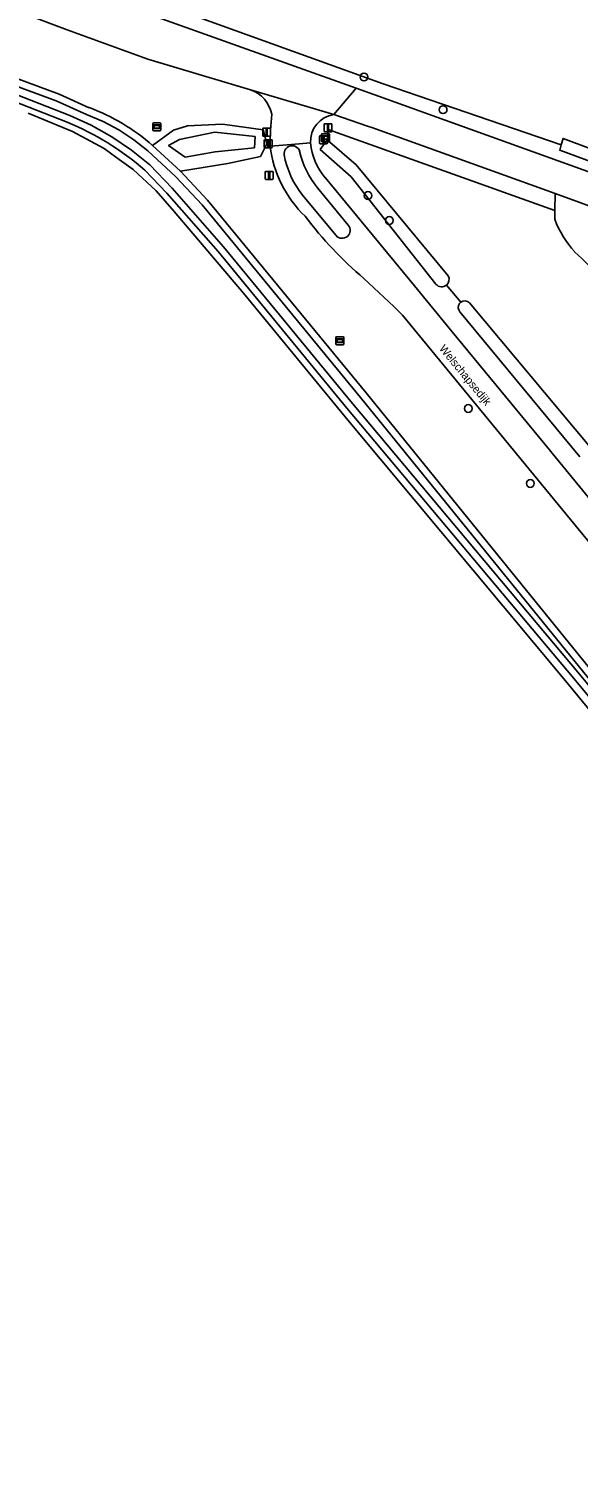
# Model space of a CAD drawing. Extents: x 156061 to 157804, y 383437 to 385640.
# Drawn here: x 156563.1 to 156631.9, y 384902.7 to 385081.3 of the extents above; entities that cross this region are included whole.
import ezdxf

# ---------------------------------------------------------------- set-up
doc = ezdxf.new("R2010")
doc.units = 0
for name, color, linetype in [('IMGEO_Afsluitpaal', 7, 'Continuous'), ('IMGEO_Berm_groen', 7, 'Continuous'), ('IMGEO_Boom', 7, 'Continuous'), ('IMGEO_Fietspad_gesloten', 7, 'Continuous'), ('IMGEO_Fietspad_open', 7, 'Continuous'), ('IMGEO_Grasland_overig', 7, 'Continuous'), ('IMGEO_Groenvoorziening', 7, 'Continuous'), ('IMGEO_Loofbos', 7, 'Continuous'), ('IMGEO_Oever', 7, 'Continuous'), ('IMGEO_Openbare_ruimte_label', 7, 'Continuous'), ('IMGEO_Rijbaan_lokaal_gesloten', 7, 'Continuous'), ('IMGEO_Rijbaan_lokaal_open', 7, 'Continuous'), ('IMGEO_Verkeersbordpaal', 7, 'Continuous'), ('IMGEO_Verkeerseiland_open', 7, 'Continuous'), ('IMGEO_Verklikker', 7, 'Continuous'), ('IMGEO_Waterloop', 7, 'Continuous')]:
    doc.layers.add(name, color=color, linetype=linetype)

msp = doc.modelspace()

# ---------------------------------------------------------------- linework, layer by layer
at = {"layer": 'IMGEO_Afsluitpaal'}
for p, q in [((156592.74, 385067.38), (156593.53, 385067.38)), ((156593.53, 385067.38), (156592.74, 385067.38)), ((156592.64, 385066.48), (156592.64, 385067.28)), ((156592.64, 385067.28), (156592.64, 385066.48)), ((156593.53, 385066.38), (156592.74, 385066.38)), ((156592.74, 385066.38), (156593.53, 385066.38)), ((156593.63, 385067.28), (156593.63, 385066.48)), ((156593.63, 385066.48), (156593.63, 385067.28))]:
    msp.add_line(p, q, dxfattribs=at)
msp.add_lwpolyline([(156593.06, 385067.26), (156593.21, 385067.26), (156593.21, 385066.51), (156593.06, 385066.51), (156593.06, 385067.26)], dxfattribs=at)
for centre, start, end in [((156592.74, 385067.28), 90, 180), ((156592.74, 385067.28), 90, 180), ((156593.53, 385067.28), 0, 90), ((156593.53, 385067.28), 360, 90), ((156592.74, 385066.48), 180, 270), ((156592.74, 385066.48), 180, 270), ((156593.53, 385066.48), 270, 0), ((156593.53, 385066.48), 270, 0)]:
    msp.add_arc(centre, 0.1, start, end, dxfattribs=at)
at = {"layer": 'IMGEO_Berm_groen'}
for points in [[(156614.11, 385049.31), (156603.5, 385062.72), (156599.64, 385066.17), (156600.1, 385066.78), (156600.53, 385067.34), (156600.64, 385068.65), (156628.99, 385058.53), (156629, 385060.65), (156606.09, 385068.91), (156605.55, 385069.09), (156601.32, 385070.53)], [(156600.26, 385062.64), (156611.41, 385049.1), (156616.13, 385043.37), (156628.31, 385028.6), (156628.66, 385028.19), (156634.53, 385021.05), (156651.9, 385000), (156717.24, 384920.7), (156766.23, 384861.24), (156857.95, 384750), (156913.26, 384682.92), (156945.25, 384644.12), (156951.65, 384636.45), (156952.01, 384636.1)], [(156617.04, 385046.91), (156617.2, 385047.08), (156615.41, 385049.21)], [(156632.12, 385027.75), (156617.11, 385045.87)]]:
    msp.add_lwpolyline(points, dxfattribs=at)
for centre, radius, start, end in [((156601.86, 385067.14), 3.44, 99.135, 182.563), ((156606.15, 385067.67), 7.75, 185.1159, 220.5408), ((156614.81, 385049.94), 0.942, 221.7637, 309.6405), ((156617.7, 385046.43), 0.815, 144.1901, 223.9343)]:
    msp.add_arc(centre, radius, start, end, dxfattribs=at)
at = {"layer": 'IMGEO_Boom'}
for centre in [(156605.11, 385075.21), (156615, 385071.13), (156605.6, 385060.4), (156608.27, 385057.28), (156618.16, 385033.78), (156625.91, 385024.41)]:
    msp.add_circle(centre, 0.489, dxfattribs=at)
at = {"layer": 'IMGEO_Fietspad_gesloten'}
for points in [[(156598.43, 385066.98), (156596.03, 385066.78), (156593.38, 385066.58)], [(156913.26, 384682.92), (156857.95, 384750), (156766.23, 384861.24), (156717.24, 384920.7), (156651.9, 385000), (156634.53, 385021.05), (156628.66, 385028.19), (156628.31, 385028.6), (156616.13, 385043.37), (156611.41, 385049.1), (156600.26, 385062.64)], [(156601.61, 385055.39), (156597.42, 385060.46)], [(156599.31, 385061.36), (156603.14, 385056.71)], [(156605.09, 385050.03), (156608.82, 385046.51), (156609.37, 385045.98), (156609.93, 385045.44), (156647.34, 385000), (156714.45, 384918.5), (156763.61, 384858.81), (156853.32, 384750), (156910.52, 384680.62), (156937.97, 384647.33)]]:
    msp.add_lwpolyline(points, dxfattribs=at)
for centre, radius, start, end in [((156607.94, 385068.37), 14.68, 186.9996, 226.026), ((156596.12, 385065.62), 1.01, 94.4691, 187.3279), ((156596.09, 385065.59), 1.04, 20.9304, 92.8641), ((156607.81, 385068.36), 11.02, 192.6008, 219.4784), ((156606.15, 385067.67), 7.75, 185.1159, 220.5408), ((156606.42, 385067.61), 11.5, 190.6035, 218.4404), ((156637.68, 385088.16), 50.16, 217.2427, 229.4737), ((156602.37, 385056.06), 1.01, 221.1018, 40.3826)]:
    msp.add_arc(centre, radius, start, end, dxfattribs=at)
at = {"layer": 'IMGEO_Fietspad_open'}
for points in [[(156601.32, 385070.53), (156590.93, 385073.63)], [(156593.38, 385066.58), (156596.03, 385066.78), (156598.43, 385066.98)]]:
    msp.add_lwpolyline(points, dxfattribs=at)
for centre, radius, start, end in [((156589.47, 385069.69), 4.2, 12.2727, 69.6849), ((156628.6, 385066.88), 35.22, 173.9637, 180.4885), ((156601.86, 385067.14), 3.44, 99.135, 182.563)]:
    msp.add_arc(centre, radius, start, end, dxfattribs=at)
at = {"layer": 'IMGEO_Grasland_overig'}
msp.add_lwpolyline([(156632.09, 385059.53), (156629, 385060.65), (156628.99, 385058.53), (156628.98, 385057.43)], dxfattribs=at)
for centre, radius, start, end in [((156640.28, 385061.53), 12.01, 199.9286, 222.6911), ((156680.81, 385103.13), 70.08, 225.225, 241.5085)]:
    msp.add_arc(centre, radius, start, end, dxfattribs=at)
at = {"layer": 'IMGEO_Groenvoorziening'}
for points in [[(156590.93, 385073.63), (156578.06, 385077.45), (156567.97, 385081.12), (156557.53, 385085.07), (156500, 385105.74), (156431.78, 385130.12), (156326.22, 385167.86), (156324.12, 385168.82), (156320.16, 385170.64)], [(156316.34, 385168.65), (156316.47, 385168.61), (156317.11, 385168.38), (156326.93, 385164.88), (156430.96, 385127.58), (156429.85, 385123.97), (156435.06, 385119.83), (156500, 385096.91), (156553.67, 385077.98), (156566.96, 385073.06), (156570.74, 385071.38)], [(156695.72, 385041.75), (156689.55, 385043.91), (156629.6, 385066.07), (156629.79, 385066.73), (156607.49, 385074.38), (156566.3, 385089.23)], [(156566.3, 385089.23), (156607.49, 385074.38), (156629.79, 385066.73), (156630.02, 385067.53), (156690.52, 385044.95), (156696.35, 385043.19)], [(156569.75, 385086.11), (156604.14, 385073.81), (156606.92, 385072.81), (156634.59, 385062.86), (156662.26, 385052.85), (156695.62, 385040.8)], [(156567.98, 385069.56), (156552.81, 385075.49)], [(156563.11, 385070.71), (156568.65, 385068.4), (156572.59, 385066.26), (156574.17, 385065.13), (156576.25, 385063.65), (156579.11, 385060.99), (156581.38, 385058.42), (156590.03, 385048.18), (156603.33, 385032.02), (156630.11, 385000), (156664.3, 384958.48)], [(156719.79, 384891.58), (156704.18, 384910.35), (156680.54, 384938.81), (156675.71, 384944.62), (156664.3, 384958.48), (156630.11, 385000), (156603.33, 385032.02), (156590.03, 385048.18), (156581.38, 385058.42), (156579.11, 385060.99), (156576.25, 385063.65), (156574.17, 385065.13), (156572.59, 385066.26), (156568.65, 385068.4), (156563.11, 385070.71)], [(156578.66, 385066.65), (156581.27, 385068.56), (156583.03, 385069.11), (156587.41, 385069.33), (156592.51, 385068.62), (156592.95, 385066.88), (156592.16, 385065.26), (156588.06, 385064.39), (156582.15, 385063.43), (156585.55, 385059.83), (156605.37, 385035.73), (156634.41, 385000), (156674.27, 384951.34), (156673.48, 384950.41), (156679.88, 384942.66), (156680.72, 384943.26), (156697.98, 384923.07), (156706.71, 384912.4), (156835.46, 384755.03)], [(156658.27, 384967.54), (156631.39, 385000), (156602.97, 385033.81), (156586.86, 385053.4), (156580.46, 385060.7), (156577.71, 385063.59)], [(156763.61, 384858.81), (156714.45, 384918.5), (156647.34, 385000), (156609.93, 385045.44), (156609.37, 385045.98), (156608.82, 385046.51), (156605.09, 385050.03)]]:
    msp.add_lwpolyline(points, dxfattribs=at)
for points in [[(156588.06, 385064.39), (156592.16, 385065.26), (156592.95, 385066.88), (156592.51, 385068.62), (156587.41, 385069.33), (156583.03, 385069.11), (156581.27, 385068.56), (156578.66, 385066.65), (156582.15, 385063.43)], [(156582.75, 385065.21), (156580.66, 385066.66), (156582.02, 385067.42), (156586.46, 385068.33), (156591.48, 385067.77), (156591.39, 385066.37), (156586.48, 385065.86)]]:
    msp.add_lwpolyline(points, close=True, dxfattribs=at)
for centre, radius, start, end in [((156589.47, 385069.69), 4.2, 12.2727, 69.6849), ((156561.98, 385047.76), 25.2, 48.5596, 69.6683), ((156554.66, 385036.95), 35.22, 49.1343, 67.7901), ((156628.6, 385066.88), 35.22, 173.9637, 180.4885), ((156607.94, 385068.37), 14.68, 186.9996, 226.026), ((156637.68, 385088.16), 50.16, 217.2427, 229.4737)]:
    msp.add_arc(centre, radius, start, end, dxfattribs=at)
at = {"layer": 'IMGEO_Loofbos'}
for points in [[(156628.98, 385057.43), (156628.99, 385058.53), (156600.64, 385068.65), (156600.53, 385067.34), (156604.12, 385064.23), (156615.65, 385050.37)], [(156615.41, 385049.21), (156617.2, 385047.08)], [(156618.31, 385046.97), (156633.42, 385028.9)]]:
    msp.add_lwpolyline(points, dxfattribs=at)
for centre, radius, start, end in [((156640.28, 385061.53), 12.01, 199.9286, 222.6911), ((156680.81, 385103.13), 70.08, 225.225, 241.5085), ((156614.81, 385049.94), 0.943, 309.5792, 27.3071), ((156617.7, 385046.41), 0.829, 42.3292, 126.9751)]:
    msp.add_arc(centre, radius, start, end, dxfattribs=at)
at = {"layer": 'IMGEO_Oever'}
for points in [[(156435.06, 385119.83), (156393.97, 385075.53), (156396.11, 385073.31), (156435.74, 385116.68), (156500, 385094.07), (156552.81, 385075.49), (156567.98, 385069.56)], [(156570.74, 385071.38), (156566.96, 385073.06), (156553.67, 385077.98), (156500, 385096.91), (156435.06, 385119.83)], [(156553.36, 385077.12), (156566.62, 385072.22), (156570.39, 385070.54), (156572.46, 385069.67), (156574.43, 385068.61), (156576.3, 385067.38), (156578.05, 385065.97), (156581.52, 385062.79), (156584.87, 385059.23), (156604.67, 385035.16), (156633.71, 384999.43), (156673.09, 384951.35), (156672.81, 384951.02), (156658.97, 384968.11), (156632.08, 385000.58), (156603.67, 385034.39), (156587.55, 385053.99), (156581.13, 385061.31), (156578.33, 385064.24), (156576.03, 385066.09), (156573.58, 385067.73), (156571, 385069.18), (156568.31, 385070.4), (156553.13, 385076.34)], [(156577.71, 385063.59), (156580.46, 385060.7), (156586.86, 385053.4), (156602.97, 385033.81), (156631.39, 385000), (156658.27, 384967.54), (156672.8, 384949.6), (156673.48, 384950.41), (156674.27, 384951.34), (156634.41, 385000), (156605.37, 385035.73), (156585.55, 385059.83), (156582.15, 385063.43), (156578.66, 385066.65)]]:
    msp.add_lwpolyline(points, dxfattribs=at)
for centre, radius, start, end in [((156561.98, 385047.76), 25.2, 48.5596, 69.6683), ((156554.66, 385036.95), 35.22, 49.1343, 67.7901)]:
    msp.add_arc(centre, radius, start, end, dxfattribs=at)
at = {"layer": 'IMGEO_Rijbaan_lokaal_gesloten'}
msp.add_lwpolyline([(156337.29, 385169.36), (156325.8, 385173.38), (156324.12, 385168.82), (156326.22, 385167.86), (156431.78, 385130.12), (156500, 385105.74), (156557.53, 385085.07), (156567.97, 385081.12), (156578.06, 385077.45), (156590.93, 385073.63), (156601.32, 385070.53), (156604.14, 385073.81), (156569.75, 385086.11)], dxfattribs=at)
at = {"layer": 'IMGEO_Rijbaan_lokaal_open'}
msp.add_lwpolyline([(156771.27, 385013.26), (156725.73, 385029.79), (156717.59, 385032.82), (156695.62, 385040.8), (156662.26, 385052.85), (156634.59, 385062.86), (156606.92, 385072.81), (156604.14, 385073.81), (156601.32, 385070.53), (156605.55, 385069.09), (156606.09, 385068.91), (156629, 385060.65), (156632.09, 385059.53), (156634.02, 385058.83), (156661.06, 385049.07), (156703.57, 385033.62), (156724.41, 385026.09), (156770.02, 385009.53)], dxfattribs=at)
at = {"layer": 'IMGEO_Verkeersbordpaal'}
for p, q in [((156600.11, 385068.48), (156600.11, 385069.28)), ((156600.11, 385069.28), (156600.11, 385068.48)), ((156600.21, 385069.38), (156601, 385069.38)), ((156601, 385069.38), (156600.21, 385069.38)), ((156601.1, 385069.28), (156601.1, 385068.48)), ((156601.1, 385068.48), (156601.1, 385069.28)), ((156592.44, 385067.91), (156592.44, 385068.71)), ((156592.44, 385068.71), (156592.44, 385067.91)), ((156592.54, 385068.81), (156593.33, 385068.81)), ((156593.33, 385068.81), (156592.54, 385068.81)), ((156593.33, 385067.81), (156592.54, 385067.81)), ((156592.54, 385067.81), (156593.33, 385067.81)), ((156593.43, 385068.71), (156593.43, 385067.91)), ((156593.43, 385067.91), (156593.43, 385068.71)), ((156599.55, 385066.98), (156599.55, 385067.78)), ((156599.55, 385067.78), (156599.55, 385066.98)), ((156599.65, 385067.88), (156600.44, 385067.88)), ((156600.44, 385067.88), (156599.65, 385067.88)), ((156601, 385068.38), (156600.21, 385068.38)), ((156600.21, 385068.38), (156601, 385068.38)), ((156600.54, 385067.78), (156600.54, 385066.98)), ((156600.54, 385066.98), (156600.54, 385067.78)), ((156600.44, 385066.88), (156599.65, 385066.88)), ((156599.65, 385066.88), (156600.44, 385066.88)), ((156592.74, 385062.52), (156592.74, 385063.32)), ((156592.74, 385063.32), (156592.74, 385062.52)), ((156592.84, 385063.42), (156593.63, 385063.42)), ((156593.63, 385063.42), (156592.84, 385063.42)), ((156593.63, 385062.42), (156592.84, 385062.42)), ((156592.84, 385062.42), (156593.63, 385062.42)), ((156593.73, 385063.32), (156593.73, 385062.52)), ((156593.73, 385062.52), (156593.73, 385063.32))]:
    msp.add_line(p, q, dxfattribs=at)
for points in [[(156600.53, 385069.26), (156600.68, 385069.26), (156600.68, 385068.51), (156600.53, 385068.51), (156600.53, 385069.26)], [(156592.86, 385068.69), (156593.01, 385068.69), (156593.01, 385067.94), (156592.86, 385067.94), (156592.86, 385068.69)], [(156599.97, 385067.76), (156600.12, 385067.76), (156600.12, 385067.01), (156599.97, 385067.01), (156599.97, 385067.76)], [(156593.16, 385063.29), (156593.31, 385063.29), (156593.31, 385062.54), (156593.16, 385062.54), (156593.16, 385063.29)]]:
    msp.add_lwpolyline(points, dxfattribs=at)
for centre, start, end in [((156600.21, 385069.28), 90, 180), ((156600.21, 385069.28), 90, 180), ((156601, 385069.28), 0, 90), ((156601, 385069.28), 360, 90), ((156592.54, 385068.71), 90, 180), ((156592.54, 385068.71), 90, 180), ((156592.54, 385067.91), 180, 270), ((156592.54, 385067.91), 180, 270), ((156593.33, 385068.71), 0, 90), ((156593.33, 385068.71), 360, 90), ((156593.33, 385067.91), 270, 0), ((156593.33, 385067.91), 270, 0), ((156599.65, 385067.78), 90, 180), ((156599.65, 385067.78), 90, 180), ((156600.21, 385068.48), 180, 270), ((156600.21, 385068.48), 180, 270), ((156600.44, 385067.78), 0, 90), ((156600.44, 385067.78), 360, 90), ((156601, 385068.48), 270, 0), ((156601, 385068.48), 270, 0), ((156599.65, 385066.98), 180, 270), ((156599.65, 385066.98), 180, 270), ((156600.44, 385066.98), 270, 0), ((156600.44, 385066.98), 270, 0), ((156592.84, 385063.32), 90, 180), ((156592.84, 385063.32), 90, 180), ((156592.84, 385062.52), 180, 270), ((156592.84, 385062.52), 180, 270), ((156593.63, 385063.32), 0, 90), ((156593.63, 385063.32), 360, 90), ((156593.63, 385062.52), 270, 0), ((156593.63, 385062.52), 270, 0)]:
    msp.add_arc(centre, 0.1, start, end, dxfattribs=at)
at = {"layer": 'IMGEO_Verkeerseiland_open'}
for points in [[(156597.42, 385060.46), (156601.61, 385055.39)], [(156603.14, 385056.71), (156599.31, 385061.36)]]:
    msp.add_lwpolyline(points, dxfattribs=at)
for centre, radius, start, end in [((156596.12, 385065.62), 1.01, 94.4691, 187.3279), ((156596.09, 385065.59), 1.04, 20.9304, 92.8641), ((156607.81, 385068.36), 11.02, 192.6008, 219.4784), ((156606.42, 385067.61), 11.5, 190.6035, 218.4404), ((156602.37, 385056.06), 1.01, 221.1018, 40.3826)]:
    msp.add_arc(centre, radius, start, end, dxfattribs=at)
at = {"layer": 'IMGEO_Verklikker'}
for p, q in [((156578.7, 385068.59), (156578.7, 385069.39)), ((156578.7, 385069.39), (156578.7, 385068.59)), ((156578.8, 385069.49), (156579.59, 385069.49)), ((156579.59, 385069.49), (156578.8, 385069.49)), ((156579.69, 385069.39), (156579.69, 385068.59)), ((156579.69, 385068.59), (156579.69, 385069.39)), ((156579.59, 385068.49), (156578.8, 385068.49)), ((156578.8, 385068.49), (156579.59, 385068.49)), ((156599.8, 385067.23), (156599.8, 385068.03)), ((156599.8, 385068.03), (156599.8, 385067.23)), ((156599.9, 385068.13), (156600.69, 385068.13)), ((156600.69, 385068.13), (156599.9, 385068.13)), ((156600.79, 385068.03), (156600.79, 385067.23)), ((156600.79, 385067.23), (156600.79, 385068.03)), ((156600.69, 385067.13), (156599.9, 385067.13)), ((156599.9, 385067.13), (156600.69, 385067.13)), ((156601.59, 385041.85), (156601.59, 385042.65)), ((156601.59, 385042.65), (156601.59, 385041.85)), ((156601.69, 385042.75), (156602.48, 385042.75)), ((156602.48, 385042.75), (156601.69, 385042.75)), ((156602.58, 385042.65), (156602.58, 385041.85)), ((156602.58, 385041.85), (156602.58, 385042.65)), ((156602.48, 385041.75), (156601.69, 385041.75)), ((156601.69, 385041.75), (156602.48, 385041.75))]:
    msp.add_line(p, q, dxfattribs=at)
for points in [[(156578.8, 385069.22), (156579.59, 385069.22), (156579.59, 385068.76), (156578.8, 385068.76), (156578.8, 385069.22)], [(156578.87, 385069.16), (156578.87, 385068.82), (156579.53, 385068.82), (156579.53, 385069.16), (156578.87, 385069.16)], [(156599.9, 385067.86), (156600.69, 385067.86), (156600.69, 385067.4), (156599.9, 385067.4), (156599.9, 385067.86)], [(156599.97, 385067.8), (156599.97, 385067.46), (156600.62, 385067.46), (156600.62, 385067.8), (156599.97, 385067.8)], [(156601.7, 385042.48), (156602.48, 385042.48), (156602.48, 385042.02), (156601.7, 385042.02), (156601.7, 385042.48)], [(156601.76, 385042.42), (156601.76, 385042.08), (156602.42, 385042.08), (156602.42, 385042.42), (156601.76, 385042.42)]]:
    msp.add_lwpolyline(points, dxfattribs=at)
for centre, start, end in [((156578.8, 385069.39), 90, 180), ((156578.8, 385069.39), 90, 180), ((156579.59, 385069.39), 0, 90), ((156579.59, 385069.39), 360, 90), ((156578.8, 385068.59), 180, 270), ((156578.8, 385068.59), 180, 270), ((156579.59, 385068.59), 270, 0), ((156579.59, 385068.59), 270, 0), ((156599.9, 385068.03), 90, 180), ((156599.9, 385068.03), 90, 180), ((156600.69, 385068.03), 0, 90), ((156600.69, 385068.03), 360, 90), ((156599.9, 385067.23), 180, 270), ((156599.9, 385067.23), 180, 270), ((156600.69, 385067.23), 270, 0), ((156600.69, 385067.23), 270, 0), ((156601.69, 385042.65), 90, 180), ((156601.69, 385042.65), 90, 180), ((156602.48, 385042.65), 0, 90), ((156602.48, 385042.65), 360, 90), ((156601.69, 385041.85), 180, 270), ((156601.69, 385041.85), 180, 270), ((156602.48, 385041.85), 270, 0), ((156602.48, 385041.85), 270, 0)]:
    msp.add_arc(centre, 0.1, start, end, dxfattribs=at)
at = {"layer": 'IMGEO_Waterloop'}
for points in [[(156553.13, 385076.34), (156568.31, 385070.4), (156571, 385069.18), (156573.58, 385067.73), (156576.03, 385066.09), (156578.33, 385064.24), (156581.13, 385061.31), (156587.55, 385053.99), (156603.67, 385034.39), (156632.08, 385000.58), (156658.97, 384968.11), (156672.81, 384951.02), (156673.09, 384951.35), (156633.71, 384999.43), (156604.67, 385035.16), (156584.87, 385059.23), (156581.52, 385062.79), (156578.05, 385065.97), (156576.3, 385067.38), (156574.43, 385068.61), (156572.46, 385069.67), (156570.39, 385070.54), (156566.62, 385072.22), (156553.36, 385077.12)], [(156604.12, 385064.23), (156600.53, 385067.34), (156600.1, 385066.78), (156599.64, 385066.17), (156603.5, 385062.72), (156614.11, 385049.31)], [(156630.02, 385067.53), (156629.79, 385066.73), (156629.6, 385066.07), (156689.55, 385043.91), (156695.72, 385041.75)], [(156696.35, 385043.19), (156690.52, 385044.95), (156630.02, 385067.53)], [(156615.65, 385050.37), (156604.12, 385064.23)], [(156617.2, 385047.08), (156617.04, 385046.91)], [(156633.42, 385028.9), (156618.31, 385046.97)], [(156617.11, 385045.87), (156632.12, 385027.75)]]:
    msp.add_lwpolyline(points, dxfattribs=at)
msp.add_lwpolyline([(156582.75, 385065.21), (156586.48, 385065.86), (156591.39, 385066.37), (156591.48, 385067.77), (156586.46, 385068.33), (156582.02, 385067.42), (156580.66, 385066.66)], close=True, dxfattribs=at)
for centre, radius, start, end in [((156614.81, 385049.94), 0.943, 309.5792, 27.3071), ((156614.81, 385049.94), 0.942, 221.7637, 309.6405), ((156617.7, 385046.43), 0.815, 144.1901, 223.9343), ((156617.7, 385046.41), 0.829, 42.3292, 126.9751)]:
    msp.add_arc(centre, radius, start, end, dxfattribs=at)

# ---------------------------------------------------------------- texts
at = {"layer": 'IMGEO_Openbare_ruimte_label'}
msp.add_text('Welschapsedijk', height=1, rotation=309.358, dxfattribs=at).set_placement((156614.45, 385041.24))

doc.saveas('drawing.dxf')
